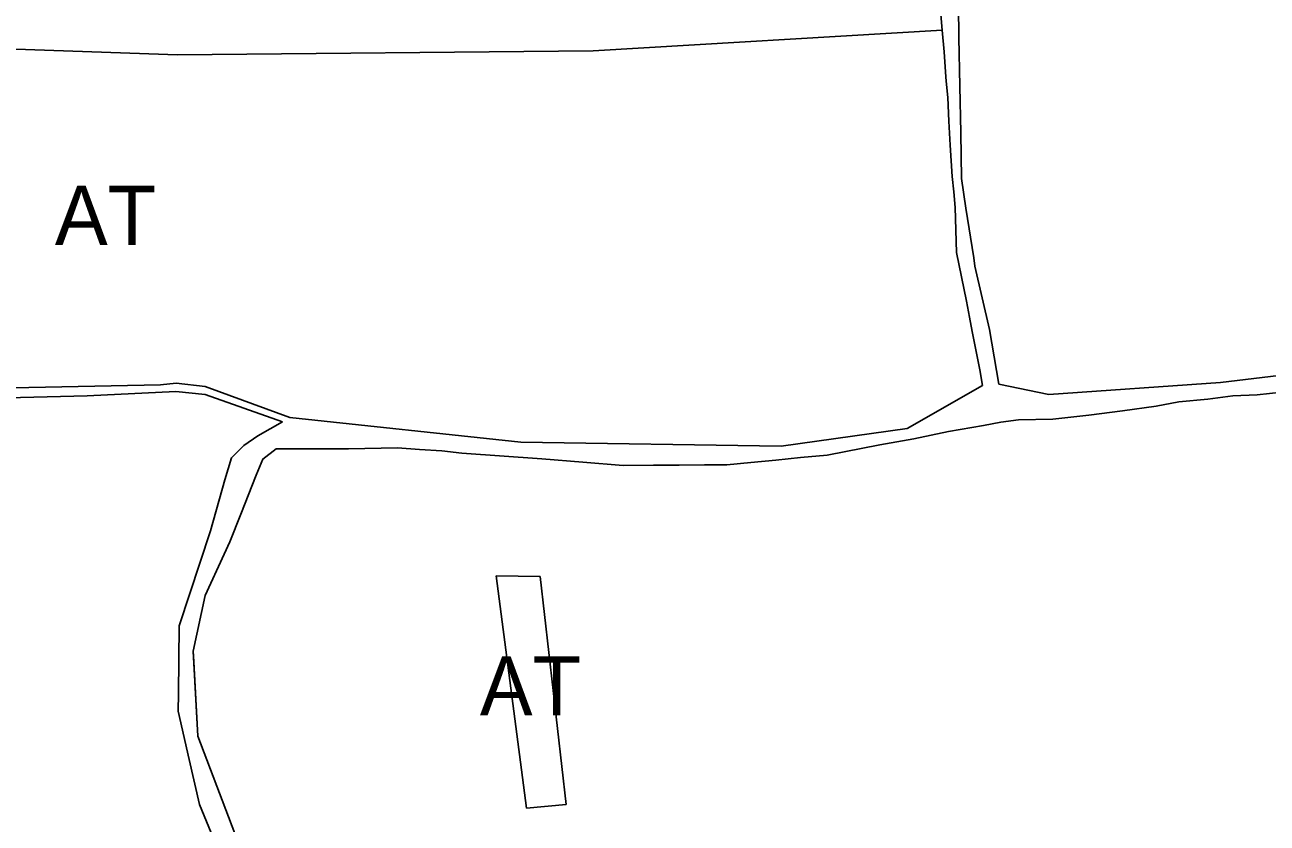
# Model space of a CAD drawing. Extents: x -555509 to -553005, y -1186756 to -1182560.
# Drawn here: x -554122.8 to -553829.3, y -1185039.8 to -1184851.2 of the extents above; entities that cross this region are included whole.
import ezdxf

# ---------------------------------------------------------------- set-up
doc = ezdxf.new("R2010")
doc.units = 0
for name, color, linetype in [('Level 26', 7, 'Continuous'), ('Level 59', 7, 'Continuous'), ('OBRYS_PLOCH', 7, 'Continuous'), ('stav_AP', 7, 'Continuous'), ('stav_AT', 7, 'Continuous'), ('stav_ZZ', 7, 'Continuous')]:
    doc.layers.add(name, color=color, linetype=linetype)

msp = doc.modelspace()

# ---------------------------------------------------------------- linework, layer by layer
at = {"layer": 'Level 26'}
for p, q in [((-553902.14, -1184854.22), (-553902.25, -1184846.67)), ((-553901.93, -1184865.66), (-553902.14, -1184854.22)), ((-553901.67, -1184876.74), (-553901.93, -1184865.66)), ((-553901.56, -1184887.51), (-553901.67, -1184876.74)), ((-553900.51, -1184894.48), (-553901.56, -1184887.51)), ((-553898.66, -1184906.26), (-553900.51, -1184894.48)), ((-553898.35, -1184908.26), (-553898.66, -1184906.26)), ((-553894.95, -1184923.21), (-553898.35, -1184908.26)), ((-553892.7, -1184936.1), (-553894.95, -1184923.21)), ((-553799.71, -1184930.69), (-553840.31, -1184935.75)), ((-553880.94, -1184938.55), (-553892.7, -1184936.1)), ((-553840.31, -1184935.75), (-553880.94, -1184938.55)), ((-553855.55, -1184941.34), (-553850.2, -1184940.25)), ((-553850.2, -1184940.25), (-553843.34, -1184939.61)), ((-553843.34, -1184939.61), (-553837.41, -1184938.84)), ((-553837.41, -1184938.84), (-553831.69, -1184938.65)), ((-553831.69, -1184938.65), (-553825.87, -1184938.03)), ((-553871.48, -1184943.44), (-553863.47, -1184942.38)), ((-553863.47, -1184942.38), (-553855.55, -1184941.34)), ((-554005.64, -1184949.81), (-554060.2, -1184943.98)), ((-553920.87, -1184950.42), (-553912.83, -1184949.06)), ((-553912.83, -1184949.06), (-553904.57, -1184947.31)), ((-554063.5, -1184951.36), (-554046.38, -1184951.38)), ((-554046.38, -1184951.38), (-554034.8, -1184951.16)), ((-554024.31, -1184951.89), (-554019.59, -1184952.44)), ((-553944.13, -1184950.79), (-554005.64, -1184949.81)), ((-553933.25, -1184952.85), (-553920.87, -1184950.42)), ((-554019.59, -1184952.44), (-554000.7, -1184953.73)), ((-554000.7, -1184953.73), (-553990.98, -1184954.51)), ((-553990.98, -1184954.51), (-553981.44, -1184955.31)), ((-553956.95, -1184955.17), (-553951.28, -1184954.65)), ((-553951.28, -1184954.65), (-553945.43, -1184954.06)), ((-553945.43, -1184954.06), (-553939.61, -1184953.44)), ((-553939.61, -1184953.44), (-553933.25, -1184952.85)), ((-553981.44, -1184955.31), (-553974.28, -1184955.24)), ((-553962.26, -1184955.2), (-553956.95, -1184955.17)), ((-554075.76, -1184976.26), (-554074.44, -1184973.35)), ((-554086.57, -1185009.18), (-554086.61, -1185013.34)), ((-554086.61, -1185013.34), (-554084, -1185024.83)), ((-554084, -1185024.83), (-554081.61, -1185035.41)), ((-554081.61, -1185035.41), (-554077.13, -1185046.17))]:
    msp.add_line(p, q, dxfattribs=at)
for points in [[(-553906.53, -1184847.81), (-553906.08, -1184852.45), (-553905.65, -1184857.61), (-553905.26, -1184863.49), (-553905.16, -1184864.48), (-553904.76, -1184868.35), (-553904.5, -1184874), (-553904.23, -1184879.65), (-553903.72, -1184887.01), (-553903.38, -1184890.69), (-553903.04, -1184894.37), (-553902.74, -1184905), (-553901.55, -1184910.75), (-553900.36, -1184916.5), (-553899.67, -1184920.24), (-553899.04, -1184923.67), (-553897.19, -1184932.74), (-553896.54, -1184936.39), (-553914.4, -1184946.57), (-553944.13, -1184950.79)], [(-554060.2, -1184943.98), (-554080.23, -1184936.63), (-554087.05, -1184935.87), (-554090.76, -1184936.24), (-554149.14, -1184937.45)], [(-554316.22, -1184944.55), (-554302.2, -1184943.12), (-554277.92, -1184939.34), (-554265.83, -1184942.99), (-554216.98, -1184941.78), (-554178.16, -1184940.73), (-554149.07, -1184939.89), (-554108.13, -1184938.86), (-554087.15, -1184937.82), (-554080.21, -1184938.55), (-554061.95, -1184944.98)], [(-554061.95, -1184944.98), (-554067.8, -1184948.3), (-554071.08, -1184950.59), (-554074, -1184953.48), (-554075.59, -1184958.74), (-554078.94, -1184970.75), (-554086.4, -1184993.22), (-554086.57, -1185009.18)], [(-553904.57, -1184947.31), (-553896.35, -1184945.85), (-553892.21, -1184945.11)], [(-553892.21, -1184945.11), (-553888.05, -1184944.56), (-553879.97, -1184944.36), (-553871.48, -1184943.44)], [(-554074.44, -1184973.35), (-554071.84, -1184966.85), (-554068.15, -1184957.6), (-554066.64, -1184953.81), (-554063.5, -1184951.36)], [(-554034.8, -1184951.16), (-554029.56, -1184951.52), (-554024.31, -1184951.89)], [(-553974.28, -1184955.24), (-553968.26, -1184955.22), (-553962.26, -1184955.2)], [(-554071.76, -1185046.22), (-554081.96, -1185019.29), (-554083.05, -1184999.19), (-554080.23, -1184986.06), (-554075.76, -1184976.26)]]:
    msp.add_lwpolyline(points, dxfattribs=at)
at = {"layer": 'OBRYS_PLOCH'}
for p, q in [((-553902.14, -1184854.22), (-553902.25, -1184846.67)), ((-553902.25, -1184846.67), (-553902.14, -1184854.22)), ((-554086.74, -1184858.26), (-554216.47, -1184853.91)), ((-553906.08, -1184852.45), (-553988.57, -1184857.33)), ((-553905.65, -1184857.61), (-553906.08, -1184852.45)), ((-553901.93, -1184865.66), (-553902.14, -1184854.22)), ((-553902.14, -1184854.22), (-553901.93, -1184865.66)), ((-553988.57, -1184857.33), (-554086.74, -1184858.26)), ((-553901.67, -1184876.74), (-553901.93, -1184865.66)), ((-553901.93, -1184865.66), (-553901.67, -1184876.74)), ((-553901.56, -1184887.51), (-553901.67, -1184876.74)), ((-553901.67, -1184876.74), (-553901.56, -1184887.51)), ((-553900.51, -1184894.48), (-553901.56, -1184887.51)), ((-553901.56, -1184887.51), (-553900.51, -1184894.48)), ((-553898.66, -1184906.26), (-553900.51, -1184894.48)), ((-553900.51, -1184894.48), (-553898.66, -1184906.26)), ((-553898.35, -1184908.26), (-553898.66, -1184906.26)), ((-553898.66, -1184906.26), (-553898.35, -1184908.26)), ((-553894.95, -1184923.21), (-553898.35, -1184908.26)), ((-553898.35, -1184908.26), (-553894.95, -1184923.21)), ((-553892.7, -1184936.1), (-553894.95, -1184923.21)), ((-553894.95, -1184923.21), (-553892.7, -1184936.1)), ((-553799.71, -1184930.69), (-553840.31, -1184935.75)), ((-553840.31, -1184935.75), (-553799.71, -1184930.69)), ((-553880.94, -1184938.55), (-553892.7, -1184936.1)), ((-553892.7, -1184936.1), (-553880.94, -1184938.55)), ((-553840.31, -1184935.75), (-553880.94, -1184938.55)), ((-553880.94, -1184938.55), (-553840.31, -1184935.75)), ((-553850.2, -1184940.25), (-553855.55, -1184941.34)), ((-553855.55, -1184941.34), (-553850.2, -1184940.25)), ((-553843.34, -1184939.61), (-553850.2, -1184940.25)), ((-553850.2, -1184940.25), (-553843.34, -1184939.61)), ((-553837.41, -1184938.84), (-553843.34, -1184939.61)), ((-553843.34, -1184939.61), (-553837.41, -1184938.84)), ((-553831.69, -1184938.65), (-553837.41, -1184938.84)), ((-553837.41, -1184938.84), (-553831.69, -1184938.65)), ((-553825.87, -1184938.03), (-553831.69, -1184938.65)), ((-553831.69, -1184938.65), (-553825.87, -1184938.03)), ((-553863.47, -1184942.38), (-553871.48, -1184943.44)), ((-553871.48, -1184943.44), (-553863.47, -1184942.38)), ((-553855.55, -1184941.34), (-553863.47, -1184942.38)), ((-553863.47, -1184942.38), (-553855.55, -1184941.34)), ((-554005.64, -1184949.81), (-554060.2, -1184943.98)), ((-554060.2, -1184943.98), (-554005.64, -1184949.81)), ((-553888.05, -1184944.56), (-553892.21, -1184945.11)), ((-553879.97, -1184944.36), (-553888.05, -1184944.56)), ((-553871.48, -1184943.44), (-553879.97, -1184944.36)), ((-553912.83, -1184949.06), (-553920.87, -1184950.42)), ((-553920.87, -1184950.42), (-553912.83, -1184949.06)), ((-553904.57, -1184947.31), (-553912.83, -1184949.06)), ((-553912.83, -1184949.06), (-553904.57, -1184947.31)), ((-554046.38, -1184951.38), (-554063.5, -1184951.36)), ((-554063.5, -1184951.36), (-554046.38, -1184951.38)), ((-554034.8, -1184951.16), (-554046.38, -1184951.38)), ((-554046.38, -1184951.38), (-554034.8, -1184951.16)), ((-554019.59, -1184952.44), (-554024.31, -1184951.89)), ((-554024.31, -1184951.89), (-554019.59, -1184952.44)), ((-553944.13, -1184950.79), (-554005.64, -1184949.81)), ((-554005.64, -1184949.81), (-553944.13, -1184950.79)), ((-553920.87, -1184950.42), (-553933.25, -1184952.85)), ((-553933.25, -1184952.85), (-553920.87, -1184950.42)), ((-554000.7, -1184953.73), (-554019.59, -1184952.44)), ((-554019.59, -1184952.44), (-554000.7, -1184953.73)), ((-553990.98, -1184954.51), (-554000.7, -1184953.73)), ((-554000.7, -1184953.73), (-553990.98, -1184954.51)), ((-553981.44, -1184955.31), (-553990.98, -1184954.51)), ((-553990.98, -1184954.51), (-553981.44, -1184955.31)), ((-553951.28, -1184954.65), (-553956.95, -1184955.17)), ((-553956.95, -1184955.17), (-553951.28, -1184954.65)), ((-553945.43, -1184954.06), (-553951.28, -1184954.65)), ((-553951.28, -1184954.65), (-553945.43, -1184954.06)), ((-553939.61, -1184953.44), (-553945.43, -1184954.06)), ((-553945.43, -1184954.06), (-553939.61, -1184953.44)), ((-553933.25, -1184952.85), (-553939.61, -1184953.44)), ((-553939.61, -1184953.44), (-553933.25, -1184952.85)), ((-553974.28, -1184955.24), (-553981.44, -1184955.31)), ((-553981.44, -1184955.31), (-553974.28, -1184955.24)), ((-553968.26, -1184955.22), (-553974.28, -1184955.24)), ((-553962.26, -1184955.2), (-553968.26, -1184955.22)), ((-553956.95, -1184955.17), (-553962.26, -1184955.2)), ((-553962.26, -1184955.2), (-553956.95, -1184955.17)), ((-554074.44, -1184973.35), (-554075.76, -1184976.26)), ((-554075.76, -1184976.26), (-554074.44, -1184973.35)), ((-554001.1, -1184981.52), (-554011.48, -1184981.39)), ((-554011.48, -1184981.39), (-554004.32, -1185036.28)), ((-553994.96, -1185035.46), (-554001.1, -1184981.52)), ((-554083.05, -1184999.19), (-554082.99, -1185000.29)), ((-554086.61, -1185013.34), (-554086.57, -1185009.18)), ((-554086.57, -1185009.18), (-554086.61, -1185013.34)), ((-554084, -1185024.83), (-554086.61, -1185013.34)), ((-554086.61, -1185013.34), (-554084, -1185024.83)), ((-554081.61, -1185035.41), (-554084, -1185024.83)), ((-554084, -1185024.83), (-554081.61, -1185035.41)), ((-554077.13, -1185046.17), (-554081.61, -1185035.41)), ((-554081.61, -1185035.41), (-554077.13, -1185046.17)), ((-554004.32, -1185036.28), (-553994.96, -1185035.46))]:
    msp.add_line(p, q, dxfattribs=at)
for points in [[(-554149.14, -1184937.45), (-554090.76, -1184936.24), (-554087.05, -1184935.87), (-554080.23, -1184936.63), (-554060.2, -1184943.98), (-554005.64, -1184949.81), (-553944.13, -1184950.79), (-553914.4, -1184946.57), (-553896.54, -1184936.39), (-553897.19, -1184932.74), (-553899.04, -1184923.67), (-553899.67, -1184920.24), (-553900.36, -1184916.5), (-553901.55, -1184910.75), (-553902.74, -1184905), (-553903.04, -1184894.37), (-553903.38, -1184890.69), (-553903.72, -1184887.01), (-553904.23, -1184879.65), (-553904.5, -1184874), (-553904.76, -1184868.35), (-553905.16, -1184864.48), (-553905.26, -1184863.49), (-553905.65, -1184857.61), (-553906.08, -1184852.45), (-553906.53, -1184847.81)], [(-553906.53, -1184847.81), (-553906.08, -1184852.45), (-553905.65, -1184857.61), (-553905.26, -1184863.49), (-553905.16, -1184864.48), (-553904.76, -1184868.35), (-553904.5, -1184874), (-553904.23, -1184879.65), (-553903.72, -1184887.01), (-553903.38, -1184890.69), (-553903.04, -1184894.37), (-553902.74, -1184905), (-553901.55, -1184910.75), (-553900.36, -1184916.5), (-553899.67, -1184920.24), (-553899.04, -1184923.67), (-553897.19, -1184932.74), (-553896.54, -1184936.39), (-553914.4, -1184946.57), (-553944.13, -1184950.79)], [(-553944.13, -1184950.79), (-553914.4, -1184946.57), (-553896.54, -1184936.39), (-553897.19, -1184932.74), (-553899.04, -1184923.67), (-553899.67, -1184920.24), (-553900.36, -1184916.5), (-553901.55, -1184910.75), (-553902.74, -1184905), (-553903.04, -1184894.37), (-553903.38, -1184890.69), (-553903.72, -1184887.01), (-553904.23, -1184879.65), (-553904.5, -1184874), (-553904.76, -1184868.35), (-553905.16, -1184864.48), (-553905.26, -1184863.49), (-553905.65, -1184857.61)], [(-554060.2, -1184943.98), (-554080.23, -1184936.63), (-554087.05, -1184935.87), (-554090.76, -1184936.24), (-554149.14, -1184937.45)], [(-554149.14, -1184937.45), (-554090.76, -1184936.24), (-554087.05, -1184935.87), (-554080.23, -1184936.63), (-554060.2, -1184943.98)], [(-554061.95, -1184944.98), (-554080.21, -1184938.55), (-554087.15, -1184937.82), (-554108.13, -1184938.86), (-554149.07, -1184939.89), (-554178.16, -1184940.73), (-554216.98, -1184941.78), (-554265.83, -1184942.99), (-554277.92, -1184939.34), (-554302.2, -1184943.12), (-554316.22, -1184944.55)], [(-554316.22, -1184944.55), (-554302.2, -1184943.12), (-554277.92, -1184939.34), (-554265.83, -1184942.99), (-554216.98, -1184941.78), (-554178.16, -1184940.73), (-554149.07, -1184939.89), (-554108.13, -1184938.86), (-554087.15, -1184937.82), (-554080.21, -1184938.55), (-554061.95, -1184944.98)], [(-554086.57, -1185009.18), (-554086.4, -1184993.22), (-554078.94, -1184970.75), (-554075.59, -1184958.74), (-554074, -1184953.48), (-554071.08, -1184950.59), (-554067.8, -1184948.3), (-554061.95, -1184944.98)], [(-554061.95, -1184944.98), (-554067.8, -1184948.3), (-554071.08, -1184950.59), (-554074, -1184953.48), (-554075.59, -1184958.74), (-554078.94, -1184970.75), (-554086.4, -1184993.22), (-554086.57, -1185009.18)], [(-553892.21, -1184945.11), (-553896.35, -1184945.85), (-553904.57, -1184947.31)], [(-553904.57, -1184947.31), (-553896.35, -1184945.85), (-553892.21, -1184945.11)], [(-553892.21, -1184945.11), (-553888.05, -1184944.56), (-553879.97, -1184944.36), (-553871.48, -1184943.44)], [(-554074.44, -1184973.35), (-554071.84, -1184966.85), (-554068.15, -1184957.6), (-554066.64, -1184953.81), (-554063.5, -1184951.36)], [(-554063.5, -1184951.36), (-554066.64, -1184953.81), (-554068.15, -1184957.6)], [(-554024.31, -1184951.89), (-554029.56, -1184951.52), (-554034.8, -1184951.16)], [(-554034.8, -1184951.16), (-554029.56, -1184951.52), (-554024.31, -1184951.89)], [(-554068.15, -1184957.6), (-554071.84, -1184966.85), (-554074.44, -1184973.35)], [(-553974.28, -1184955.24), (-553968.26, -1184955.22), (-553962.26, -1184955.2)], [(-554075.76, -1184976.26), (-554080.23, -1184986.06), (-554083.05, -1184999.19)], [(-554071.76, -1185046.22), (-554081.96, -1185019.29), (-554083.05, -1184999.19), (-554080.23, -1184986.06), (-554075.76, -1184976.26)], [(-554082.99, -1185000.29), (-554081.96, -1185019.29), (-554071.76, -1185046.22)]]:
    msp.add_lwpolyline(points, dxfattribs=at)
at = {"layer": 'stav_AP'}
for p, q in [((-553906.08, -1184852.45), (-553906.53, -1184847.81)), ((-554216.47, -1184853.91), (-554086.74, -1184858.26)), ((-553988.57, -1184857.33), (-553906.08, -1184852.45)), ((-554086.74, -1184858.26), (-553988.57, -1184857.33))]:
    msp.add_line(p, q, dxfattribs=at)
at = {"layer": 'stav_AT'}
for p, q in [((-553902.25, -1184846.67), (-553902.14, -1184854.22)), ((-554086.74, -1184858.26), (-554216.47, -1184853.91)), ((-553906.08, -1184852.45), (-553988.57, -1184857.33)), ((-553905.65, -1184857.61), (-553906.08, -1184852.45)), ((-553902.14, -1184854.22), (-553901.93, -1184865.66)), ((-553988.57, -1184857.33), (-554086.74, -1184858.26)), ((-553901.93, -1184865.66), (-553901.67, -1184876.74)), ((-553901.67, -1184876.74), (-553901.56, -1184887.51)), ((-553901.56, -1184887.51), (-553900.51, -1184894.48)), ((-553900.51, -1184894.48), (-553898.66, -1184906.26)), ((-553898.66, -1184906.26), (-553898.35, -1184908.26)), ((-553898.35, -1184908.26), (-553894.95, -1184923.21)), ((-553894.95, -1184923.21), (-553892.7, -1184936.1)), ((-553840.31, -1184935.75), (-553799.71, -1184930.69)), ((-553892.7, -1184936.1), (-553880.94, -1184938.55)), ((-553880.94, -1184938.55), (-553840.31, -1184935.75)), ((-554060.2, -1184943.98), (-554005.64, -1184949.81)), ((-554005.64, -1184949.81), (-553944.13, -1184950.79)), ((-554001.1, -1184981.52), (-554011.48, -1184981.39)), ((-554011.48, -1184981.39), (-554004.32, -1185036.28)), ((-553994.96, -1185035.46), (-554001.1, -1184981.52)), ((-554004.32, -1185036.28), (-553994.96, -1185035.46))]:
    msp.add_line(p, q, dxfattribs=at)
for points in [[(-553944.13, -1184950.79), (-553914.4, -1184946.57), (-553896.54, -1184936.39), (-553897.19, -1184932.74), (-553899.04, -1184923.67), (-553899.67, -1184920.24), (-553900.36, -1184916.5), (-553901.55, -1184910.75), (-553902.74, -1184905), (-553903.04, -1184894.37), (-553903.38, -1184890.69), (-553903.72, -1184887.01), (-553904.23, -1184879.65), (-553904.5, -1184874), (-553904.76, -1184868.35), (-553905.16, -1184864.48), (-553905.26, -1184863.49), (-553905.65, -1184857.61)], [(-554149.14, -1184937.45), (-554090.76, -1184936.24), (-554087.05, -1184935.87), (-554080.23, -1184936.63), (-554060.2, -1184943.98)]]:
    msp.add_lwpolyline(points, dxfattribs=at)
at = {"layer": 'stav_ZZ'}
for p, q in [((-553850.2, -1184940.25), (-553855.55, -1184941.34)), ((-553843.34, -1184939.61), (-553850.2, -1184940.25)), ((-553837.41, -1184938.84), (-553843.34, -1184939.61)), ((-553831.69, -1184938.65), (-553837.41, -1184938.84)), ((-553825.87, -1184938.03), (-553831.69, -1184938.65)), ((-553863.47, -1184942.38), (-553871.48, -1184943.44)), ((-553855.55, -1184941.34), (-553863.47, -1184942.38)), ((-553888.05, -1184944.56), (-553892.21, -1184945.11)), ((-553879.97, -1184944.36), (-553888.05, -1184944.56)), ((-553871.48, -1184943.44), (-553879.97, -1184944.36)), ((-553912.83, -1184949.06), (-553920.87, -1184950.42)), ((-553904.57, -1184947.31), (-553912.83, -1184949.06)), ((-554046.38, -1184951.38), (-554063.5, -1184951.36)), ((-554034.8, -1184951.16), (-554046.38, -1184951.38)), ((-554019.59, -1184952.44), (-554024.31, -1184951.89)), ((-553920.87, -1184950.42), (-553933.25, -1184952.85)), ((-554000.7, -1184953.73), (-554019.59, -1184952.44)), ((-553990.98, -1184954.51), (-554000.7, -1184953.73)), ((-553981.44, -1184955.31), (-553990.98, -1184954.51)), ((-553951.28, -1184954.65), (-553956.95, -1184955.17)), ((-553945.43, -1184954.06), (-553951.28, -1184954.65)), ((-553939.61, -1184953.44), (-553945.43, -1184954.06)), ((-553933.25, -1184952.85), (-553939.61, -1184953.44)), ((-553974.28, -1184955.24), (-553981.44, -1184955.31)), ((-553968.26, -1184955.22), (-553974.28, -1184955.24)), ((-553962.26, -1184955.2), (-553968.26, -1184955.22)), ((-553956.95, -1184955.17), (-553962.26, -1184955.2)), ((-554074.44, -1184973.35), (-554075.76, -1184976.26)), ((-554083.05, -1184999.19), (-554082.99, -1185000.29)), ((-554086.61, -1185013.34), (-554086.57, -1185009.18)), ((-554084, -1185024.83), (-554086.61, -1185013.34)), ((-554081.61, -1185035.41), (-554084, -1185024.83)), ((-554077.13, -1185046.17), (-554081.61, -1185035.41))]:
    msp.add_line(p, q, dxfattribs=at)
for points in [[(-554061.95, -1184944.98), (-554080.21, -1184938.55), (-554087.15, -1184937.82), (-554108.13, -1184938.86), (-554149.07, -1184939.89), (-554178.16, -1184940.73), (-554216.98, -1184941.78), (-554265.83, -1184942.99), (-554277.92, -1184939.34), (-554302.2, -1184943.12), (-554316.22, -1184944.55)], [(-554086.57, -1185009.18), (-554086.4, -1184993.22), (-554078.94, -1184970.75), (-554075.59, -1184958.74), (-554074, -1184953.48), (-554071.08, -1184950.59), (-554067.8, -1184948.3), (-554061.95, -1184944.98)], [(-553892.21, -1184945.11), (-553896.35, -1184945.85), (-553904.57, -1184947.31)], [(-554063.5, -1184951.36), (-554066.64, -1184953.81), (-554068.15, -1184957.6)], [(-554024.31, -1184951.89), (-554029.56, -1184951.52), (-554034.8, -1184951.16)], [(-554068.15, -1184957.6), (-554071.84, -1184966.85), (-554074.44, -1184973.35)], [(-554075.76, -1184976.26), (-554080.23, -1184986.06), (-554083.05, -1184999.19)], [(-554082.99, -1185000.29), (-554081.96, -1185019.29), (-554071.76, -1185046.22)]]:
    msp.add_lwpolyline(points, dxfattribs=at)

# ---------------------------------------------------------------- texts
at = {"layer": 'Level 59'}
for p in [(-554115.75, -1184903.2), (-554015.35, -1185014.38)]:
    msp.add_text('AT', height=14, dxfattribs=at).set_placement(p)

doc.saveas('drawing.dxf')
